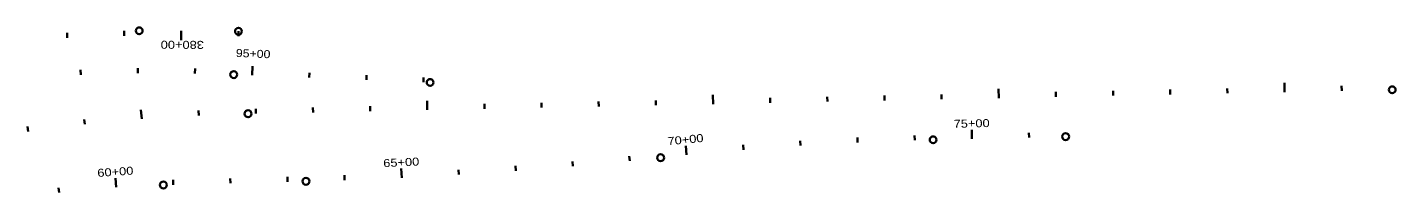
# Model space of a CAD drawing. Extents: x 2357892 to 2370172, y 6966790 to 6985499.
# Drawn here: x 2367778 to 2370172, y 6978380 to 6978669 of the extents above; entities that cross this region are included whole.
import ezdxf
from ezdxf.enums import TextEntityAlignment as Align

# ---------------------------------------------------------------- set-up
doc = ezdxf.new("R2010")
doc.units = 0
doc.header["$LTSCALE"] = 5.6
doc.layers.add('28', color=7, linetype='Continuous', lineweight=35)

msp = doc.modelspace()

# ---------------------------------------------------------------- linework, layer by layer
at = {"layer": '28'}
for p, q in [((2367847.226, 6978659.077), (2367847.751, 6978650.594)), ((2367947.151, 6978662.639), (2367947.231, 6978654.139)), ((2368047.15, 6978662.384), (2368047.08, 6978646.384)), ((2368147.149, 6978661.947), (2368147.112, 6978653.447)), ((2367871.137, 6978585.982), (2367870.783, 6978594.474)), ((2367971.102, 6978588.614), (2367971.008, 6978597.114)), ((2368071.101, 6978588.193), (2368071.267, 6978596.691)), ((2368171.047, 6978584.877), (2368171.689, 6978600.864)), ((2368270.966, 6978580.86), (2368271.307, 6978589.354)), ((2368370.885, 6978576.844), (2368371.227, 6978585.337)), ((2368470.805, 6978572.828), (2368471.146, 6978581.321)), ((2369977.194, 6978555.616), (2369976.859, 6978571.612)), ((2370077.172, 6978557.707), (2370076.994, 6978566.205)), ((2368477.522, 6978524.246), (2368477.187, 6978540.242)), ((2368777.456, 6978530.52), (2368777.279, 6978539.018)), ((2368877.434, 6978532.611), (2368877.257, 6978541.109)), ((2368977.413, 6978534.702), (2368977.078, 6978550.699)), ((2369077.391, 6978536.794), (2369077.213, 6978545.292)), ((2369177.369, 6978538.885), (2369177.191, 6978547.383)), ((2369277.347, 6978540.976), (2369277.169, 6978549.475)), ((2369377.325, 6978543.068), (2369377.147, 6978551.566)), ((2369477.303, 6978545.159), (2369476.969, 6978561.156)), ((2369577.281, 6978547.25), (2369577.104, 6978555.749)), ((2369677.259, 6978549.342), (2369677.082, 6978557.84)), ((2369777.238, 6978551.433), (2369777.06, 6978559.931)), ((2369877.216, 6978553.525), (2369877.038, 6978562.023)), ((2367977.843, 6978508.487), (2367976.599, 6978524.439)), ((2368077.643, 6978514.74), (2368077.241, 6978523.231)), ((2368177.588, 6978517.971), (2368177.41, 6978526.47)), ((2368277.566, 6978520.063), (2368277.388, 6978528.561)), ((2368377.544, 6978522.154), (2368377.366, 6978530.652)), ((2368577.5, 6978526.337), (2368577.322, 6978534.835)), ((2368677.478, 6978528.428), (2368677.3, 6978536.926)), ((2367779.048, 6978486.855), (2367777.87, 6978495.273)), ((2367878.28, 6978499.189), (2367877.36, 6978507.639)), ((2369130.476, 6978461.884), (2369129.93, 6978470.367)), ((2369230.32, 6978467.435), (2369229.923, 6978475.926)), ((2369330.247, 6978471.242), (2369329.997, 6978479.738)), ((2369430.216, 6978473.706), (2369429.836, 6978489.702)), ((2369530.188, 6978476.081), (2369529.986, 6978484.578)), ((2368831.71, 6978435.242), (2368830.861, 6978443.699)), ((2368931.153, 6978445.56), (2368929.569, 6978461.482)), ((2369030.743, 6978454.592), (2369030.05, 6978463.064)), ((2368432.846, 6978405.729), (2368432.083, 6978421.711)), ((2368532.698, 6978411.149), (2368532.182, 6978419.633)), ((2368632.471, 6978417.875), (2368631.844, 6978426.352)), ((2368732.147, 6978425.906), (2368731.409, 6978434.374)), ((2367933.144, 6978389.242), (2367932.04, 6978405.204)), ((2368033.039, 6978393.604), (2368032.82, 6978402.102)), ((2368133.006, 6978396.175), (2368132.787, 6978404.672)), ((2368232.973, 6978398.746), (2368232.754, 6978407.243)), ((2368332.931, 6978401.618), (2368332.637, 6978410.112)), ((2367833.608, 6978379.736), (2367832.579, 6978388.173))]:
    msp.add_line(p, q, dxfattribs=at)
for centre in [(2367973.546, 6978662.706), (2368147.149, 6978661.947), (2368138.792, 6978586.173), (2368482.455, 6978572.36), (2370165.502, 6978559.555), (2368163.993, 6978517.687), (2369362.383, 6978472.096), (2369594.163, 6978477.6), (2368885.7, 6978440.855), (2368885.711, 6978440.856), (2368015.799, 6978393.161), (2368265.158, 6978399.574)]:
    msp.add_circle(centre, 6, dxfattribs=at)

# ---------------------------------------------------------------- texts
for s, rotation, width, p in [('380+00', 179.75, 1.2, (2368048.96, 6978645.23)), ('95+00', 357.698, 1.15, (2368172.574, 6978615.84)), ('75+00', 1.36, 1.2, (2369429.908, 6978493.705)), ('70+00', 5.682, 1.2, (2368929.866, 6978465.531)), ('60+00', 3.956, 1.2, (2367932.248, 6978409.228)), ('65+00', 2.732, 1.2, (2368432.227, 6978425.723))]:
    msp.add_text(s, height=14, rotation=rotation, dxfattribs=dict(at, width=width)).set_placement(p, align=Align.CENTER)

doc.saveas('drawing.dxf')
